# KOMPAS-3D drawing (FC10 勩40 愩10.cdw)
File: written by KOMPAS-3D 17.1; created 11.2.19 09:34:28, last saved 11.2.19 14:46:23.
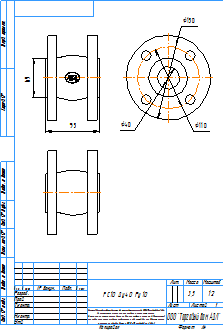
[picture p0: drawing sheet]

Sheet 1: A4, portrait

Title block, sheet 1: name: FC10 Ду40 Ру10; mass: 3,5; sheets: 1; sheet format: A4; stored path: \\adlc.lan\data\АДЛ_ПКД\3D-модели\ADL production\Гибкие вставки серии FC\FC10\KOMPAS 2D\FC10 Ду40 Ру10.cdw

Views: Вид 1
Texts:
  kka
  adl
  Рама для чертежей
  Лит-Масса-Масштаб
  Материал-Предприятие
  Масштаб
  Изм.
  Лист
  № докум.
  Подп.
  Дата
  Лит.
  Разраб.
  Пров.
  Т.контр.
  Листов
  Внимание! Данный продукт является объектом авторского права ООО «Торговый Дом АДЛ».
  Запрещается изменение, копирование, распространение
  (в том числе путем копирования на другие сайты и ресурсы в Интернете)
  или любое иное использование информации и объектов без предварительного
  согласия правообладателя (ООО «Торговый Дом АДЛ»).
  Н.контр.
  Утв.
  ООО "Торговый дом АДЛ"
  Изменение
  Номер документа
  Подпись
  Обозначение документа
  Наименование изделия
  Масса изделия по ГОСТ 2.109-73
  Порядковый номер листа
  Общее количество листов в документе
  Характер работы, выполненной лицом, подписавшим документ
  Наименование или индекс предприятия, выпускающего документ
  Инв. № подл.
  Подп. и дата
  Взам. инв. №
  Инв. № дубл.
  Инвентарный номер подлинника по ГОСТ 2.501-68
  Подпись принявшего подлинник в отдел технической документации
  Инвентарный номер подлинника, взамен которого выпущен данный подлинник
  Инвентарный номер дубликата по ГОСТ 2.502-68
  Подпись принявшего дубликат в отдел технической документации
  Справ. №
  Перв. примен.
  Обозначение документа, взамен или на основании которого выпущен данный документ
  Обозначение документа, в котором впервые записан данный документ
  Подпись лица, копировавшего чертеж
  Обозначение формата листа
  !Рама для чертежа
Dimensions and other numbers on the sheet: 95; 69; 40; 110; 150; 1:2; 1; 3,5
